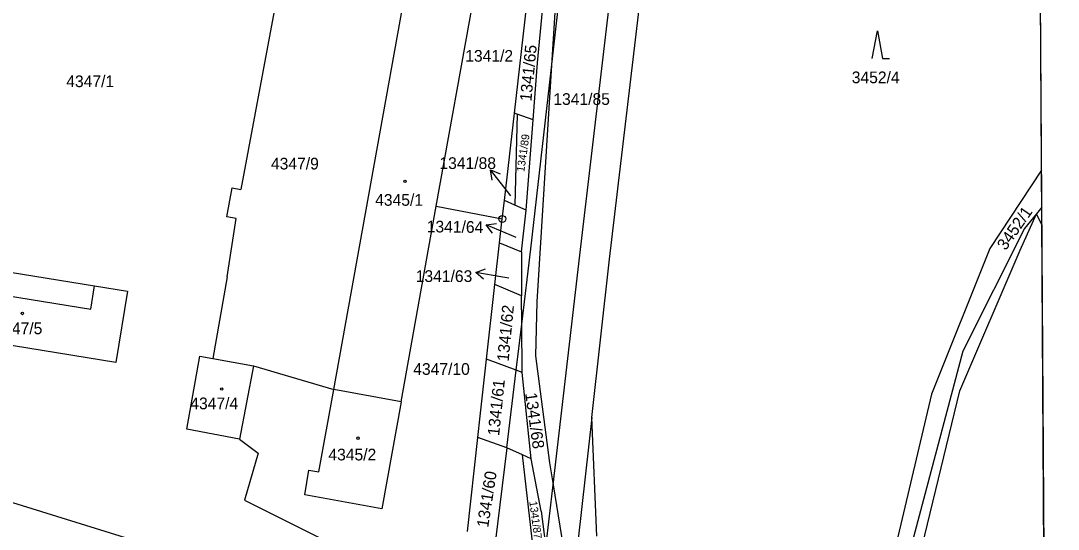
# Model space of a CAD drawing. Extents: x -735036 to -734743, y -1144813 to -1144181.
# Drawn here: x -734893.7 to -734743, y -1144472.3 to -1144398.5 of the extents above; entities that cross this region are included whole.
import ezdxf

# ---------------------------------------------------------------- set-up
doc = ezdxf.new("R2010")
doc.units = 0
for name, color, linetype in [('000_rozpiska', 7, 'Continuous'), ('BPEJ', 7, 'Continuous'), ('Katastr_HRANICE DRÁHY', 7, 'Continuous'), ('Katastr_Hranice parcel', 7, 'Continuous'), ('Katastr_Parcelní čísla', 7, 'Continuous'), ('Katastr_Slučkované čáry', 7, 'Continuous'), ('Katastr_Značky kultur', 7, 'Continuous'), ('ZÁBORY_dočasné', 7, 'Continuous')]:
    doc.layers.add(name, color=color, linetype=linetype)

msp = doc.modelspace()

# ---------------------------------------------------------------- linework, layer by layer
at = {"layer": '000_rozpiska'}
msp.add_line((-734743.05, -1144810.64), (-734746.94, -1144180.65), dxfattribs=at)
at = {"layer": 'BPEJ'}
msp.add_lwpolyline([(-734745.43, -1144425.57), (-734746.2, -1144426.51), (-734747.96, -1144428.65), (-734756.9, -1144446.43), (-734767.25, -1144485.5)], dxfattribs=at)
at = {"layer": 'Defpoints'}
msp.add_line((-734743.05, -1144810.64), (-734745.64, -1144390.65), dxfattribs=at)
at = {"layer": 'Katastr_HRANICE DRÁHY'}
for p, q in [((-734863.76, -1144426.93), (-734862.99, -1144422.76)), ((-734862.99, -1144422.76), (-734861.74, -1144422.99)), ((-734862.39, -1144427.18), (-734863.76, -1144426.93)), ((-734863.72, -1144435.68), (-734862.39, -1144427.18)), ((-734861.92, -1144459.22), (-734859.22, -1144461.28)), ((-734859.22, -1144461.28), (-734861.21, -1144468.1)), ((-734861.21, -1144468.1), (-734830.02, -1144483.57))]:
    msp.add_line(p, q, dxfattribs=at)
for points in [[(-734856.46, -1144394.74), (-734861.74, -1144422.99)], [(-734863.72, -1144435.68), (-734865.79, -1144447.52)], [(-734869.58, -1144457.79), (-734867.66, -1144447.19)], [(-734867.66, -1144447.19), (-734865.79, -1144447.52)], [(-734861.92, -1144459.22), (-734869.58, -1144457.79)]]:
    msp.add_lwpolyline(points, dxfattribs=at)
at = {"layer": 'Katastr_Hranice parcel'}
for p, q in [((-734833.36, -1144425.43), (-734827.31, -1144391.78)), ((-734822.01, -1144411.9), (-734820.19, -1144396.14)), ((-734823.77, -1144427.26), (-734823.46, -1144424.57))]:
    msp.add_line(p, q, dxfattribs=at)
for points in [[(-734848.25, -1144452.02), (-734837.31, -1144391.22)], [(-734815.76, -1144391.08), (-734816.67, -1144405.73)], [(-734808.21, -1144433.11), (-734803.24, -1144391.01)], [(-734818.66, -1144404.58), (-734817.92, -1144397.01)], [(-734819.31, -1144412.88), (-734818.66, -1144404.58)], [(-734816.67, -1144405.73), (-734818.75, -1144439.28)], [(-734823.46, -1144424.57), (-734822.01, -1144411.9)], [(-734821.62, -1144412.04), (-734822.01, -1144411.9)], [(-734821.62, -1144412.04), (-734821.97, -1144425.24)], [(-734819.31, -1144412.88), (-734821.62, -1144412.04)], [(-734820.32, -1144425.99), (-734819.31, -1144412.88)], [(-734745.46, -1144420.16), (-734752.99, -1144431.55)], [(-734821.97, -1144425.24), (-734823.46, -1144424.57)], [(-734820.32, -1144425.99), (-734821.97, -1144425.24)], [(-734838.46, -1144453.82), (-734833.36, -1144425.43)], [(-734833.36, -1144425.43), (-734823.77, -1144427.26)], [(-734820.97, -1144432.03), (-734820.32, -1144425.99)], [(-734748.56, -1144431.79), (-734746.2, -1144426.51)], [(-734746.2, -1144426.51), (-734747.96, -1144428.65)], [(-734745.43, -1144425.57), (-734746.2, -1144426.51)], [(-734745.41, -1144428.13), (-734746.2, -1144426.51)], [(-734824.17, -1144430.72), (-734823.77, -1144427.26)], [(-734747.96, -1144428.65), (-734756.9, -1144446.43)], [(-734824.84, -1144436.79), (-734824.17, -1144430.72)], [(-734824.17, -1144430.72), (-734820.97, -1144432.03)], [(-734820.97, -1144432.03), (-734820.97, -1144438.4)], [(-734752.99, -1144431.55), (-734761.43, -1144452.7)], [(-734757.32, -1144452.22), (-734748.56, -1144431.79)], [(-734900.62, -1144434.11), (-734883, -1144436.95)], [(-734810.79, -1144456.08), (-734808.21, -1144433.11)], [(-734883, -1144436.95), (-734878.19, -1144437.75)], [(-734826.04, -1144447.62), (-734824.84, -1144436.79)], [(-734820.97, -1144438.4), (-734824.84, -1144436.79)], [(-734878.19, -1144437.75), (-734879.9, -1144448.12)], [(-734820.94, -1144442.53), (-734820.97, -1144438.4)], [(-734818.75, -1144439.28), (-734818.94, -1144447.13)], [(-734820.88, -1144449.56), (-734820.94, -1144442.53)], [(-734879.9, -1144448.12), (-734907.55, -1144443.6)], [(-734865.79, -1144447.52), (-734859.89, -1144448.56)], [(-734826.96, -1144455.87), (-734826.04, -1144447.62)], [(-734821.75, -1144449.23), (-734826.04, -1144447.62)], [(-734818.94, -1144447.13), (-734816.91, -1144462.68)], [(-734756.9, -1144446.43), (-734767.25, -1144485.5)], [(-734859.89, -1144448.56), (-734861.92, -1144459.22)], [(-734859.89, -1144448.56), (-734848.25, -1144452.02)], [(-734820.88, -1144449.56), (-734821.75, -1144449.23)], [(-734819.57, -1144462.07), (-734820.88, -1144449.56)], [(-734850.4, -1144463.96), (-734848.25, -1144452.02)], [(-734838.46, -1144453.82), (-734848.25, -1144452.02)], [(-734764.76, -1144482.73), (-734757.32, -1144452.22)], [(-734838.46, -1144453.82), (-734841.25, -1144469.34)], [(-734761.43, -1144452.7), (-734769.6, -1144487.14)], [(-734827.3, -1144458.97), (-734826.96, -1144455.87)], [(-734810.79, -1144456.08), (-734813.74, -1144482.35)], [(-734810.02, -1144473.32), (-734810.79, -1144456.08)], [(-734828.81, -1144472.64), (-734827.3, -1144458.97)], [(-734823.12, -1144460.47), (-734827.3, -1144458.97)], [(-734820.84, -1144461.5), (-734823.12, -1144460.47)], [(-734819.57, -1144462.07), (-734820.84, -1144461.5)], [(-734819.07, -1144476.7), (-734820.84, -1144461.5)], [(-734818.11, -1144469.69), (-734819.57, -1144462.07)], [(-734816.91, -1144462.68), (-734816.4, -1144465.87)], [(-734852.45, -1144467.31), (-734851.86, -1144463.72)], [(-734851.86, -1144463.72), (-734850.4, -1144463.96)], [(-734816.4, -1144465.87), (-734813.74, -1144482.35)], [(-734902.72, -1144466.02), (-734842.51, -1144484.69)], [(-734841.25, -1144469.34), (-734852.45, -1144467.31)], [(-734818.11, -1144469.69), (-734817.45, -1144474.93)]]:
    msp.add_lwpolyline(points, dxfattribs=at)
at = {"layer": 'Katastr_Parcelní čísla'}
for p, q in [((-734825.26, -1144421.61), (-734825.46, -1144420.12)), ((-734822.54, -1144423.89), (-734823.01, -1144423.28)), ((-734825.21, -1144429.31), (-734826.12, -1144428.11)), ((-734821.74, -1144429.95), (-734822.43, -1144429.66)), ((-734826.48, -1144436), (-734827.63, -1144435.04)), ((-734822.84, -1144435.88), (-734823.69, -1144435.73))]:
    msp.add_line(p, q, dxfattribs=at)
for points in [[(-734823.01, -1144423.28), (-734825.46, -1144420.12), (-734824.07, -1144420.69)], [(-734822.43, -1144429.66), (-734826.12, -1144428.11), (-734824.63, -1144427.92)], [(-734823.69, -1144435.73), (-734827.63, -1144435.04), (-734826.22, -1144434.52)]]:
    msp.add_lwpolyline(points, dxfattribs=at)
at = {"layer": 'Katastr_Slučkované čáry'}
for points in [[(-734816.67, -1144405.73), (-734815.01, -1144391.08)], [(-734812.53, -1144432.52), (-734807.63, -1144391.03)], [(-734819.61, -1144431.61), (-734816.67, -1144405.73)], [(-734820.94, -1144442.53), (-734819.61, -1144431.61)], [(-734816.4, -1144465.87), (-734812.53, -1144432.52)], [(-734883.5, -1144440.36), (-734883, -1144436.95)], [(-734901.18, -1144437.52), (-734883.5, -1144440.36)], [(-734821.75, -1144449.23), (-734820.94, -1144442.53)], [(-734823.12, -1144460.47), (-734821.75, -1144449.23)], [(-734823.12, -1144460.47), (-734824.8, -1144474.27)], [(-734817.45, -1144474.93), (-734816.4, -1144465.87)]]:
    msp.add_lwpolyline(points, dxfattribs=at)
at = {"layer": 'Katastr_Značky kultur'}
msp.add_line((-734823.82, -1144427.26), (-734823.72, -1144427.26), dxfattribs=at)
msp.add_lwpolyline([(-734770.05, -1144403.98), (-734769.3, -1144399.98), (-734768.55, -1144403.98), (-734767.55, -1144403.98)], dxfattribs=at)
for centre, radius in [((-734837.9, -1144421.79), 0.175), ((-734823.77, -1144427.26), 0.499), ((-734893.45, -1144440.98), 0.175), ((-734864.51, -1144451.96), 0.175), ((-734844.73, -1144459.08), 0.175)]:
    msp.add_circle(centre, radius, dxfattribs=at)

# ---------------------------------------------------------------- texts
at = {"layer": 'Katastr_Parcelní čísla'}
for s, p in [('1341/2', (-734829.15, -1144404.44)), ('4347/1', (-734887.08, -1144408.13)), ('3452/4', (-734773.03, -1144407.56)), ('1341/85', (-734816.36, -1144410.71)), ('4347/9', (-734857.36, -1144420.08)), ('1341/88', (-734832.9, -1144420.01)), ('4345/1', (-734842.23, -1144425.35)), ('1341/63', (-734836.34, -1144436.41)), ('4347/5', (-734897.5, -1144443.99)), ('4347/10', (-734836.7, -1144449.89)), ('4347/4', (-734869.07, -1144454.88)), ('4345/2', (-734849.02, -1144462.31))]:
    msp.add_text(s, height=1.7, dxfattribs=at).set_placement(p)
for s, height, rotation, p in [('1341/65', 1.7, 84.3541, (-734819.55, -1144410.25)), ('1341/89', 1.14, 81.8181, (-734820.58, -1144420.49)), ('3452/1', 1.7, 55.1362, (-734750.68, -1144431.93)), ('1341/64', 1.7, 359.3069, (-734834.75, -1144429.2)), ('1341/62', 1.7, 84.5309, (-734822.85, -1144448.01)), ('1341/61', 1.7, 84.0626, (-734824.23, -1144458.8)), ('1341/68', 1.7, 277.952, (-734820.45, -1144452.58)), ('1341/60', 1.7, 81.2094, (-734825.82, -1144472.13)), ('1341/87', 1.14, 277.4791, (-734819.85, -1144468.28))]:
    msp.add_text(s, height=height, rotation=rotation, dxfattribs=at).set_placement(p)
at = {"layer": 'ZÁBORY_dočasné'}
msp.add_text('DOČASNÝ ZÁBOR POZEMKU (DZ-14)', height=2, rotation=336.28, dxfattribs=at).set_placement((-734923.53, -1144472.47))

doc.saveas('drawing.dxf')
